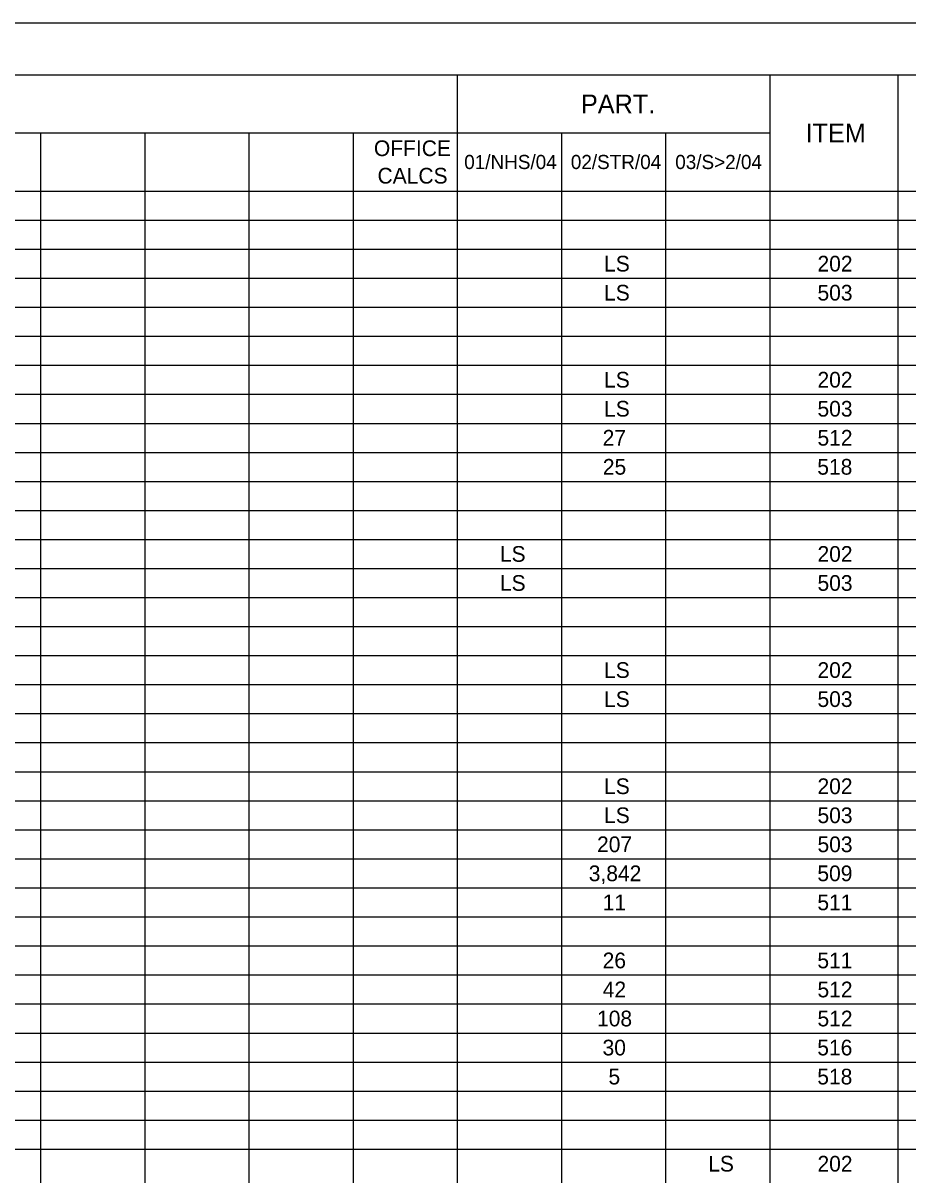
# Model space of a CAD drawing. Extents: x 0 to 34, y 0 to 22.
# Drawn here: x 8.36 to 16.9, y 10.89 to 22 of the extents above; entities that cross this region are included whole.
import ezdxf

# ---------------------------------------------------------------- set-up
doc = ezdxf.new("R2010")
doc.units = 0
for name, color, linetype in [('SH_Border', 7, 'Continuous'), ('SH_Cut_Line', 7, 'Continuous'), ('SH_Text', 7, 'Continuous')]:
    doc.layers.add(name, color=color, linetype=linetype)

msp = doc.modelspace()

# ---------------------------------------------------------------- linework, layer by layer
at = {"layer": 'SH_Border'}
msp.add_lwpolyline([(1.5, 21.5), (33.5, 21.5), (33.5, 0.5), (1.5, 0.5)], close=True, dxfattribs=at)
at = {"layer": 'SH_Cut_Line'}
msp.add_lwpolyline([(0, 0), (34, 0), (34, 22), (0, 22)], close=True, dxfattribs=at)
at = {"layer": 'SH_Text'}
for p, q in [((1.5, 21.5), (32, 21.5)), ((12.55, 21.5), (12.55, 0.502)), ((15.564, 21.5), (15.564, 0.502)), ((16.799, 21.5), (16.799, 0.502)), ((1.5, 20.94), (15.564, 20.94)), ((8.532, 20.94), (8.532, 0.502)), ((9.537, 20.94), (9.537, 0.502)), ((10.541, 20.94), (10.541, 0.502)), ((11.546, 20.94), (11.546, 0.502)), ((13.555, 20.94), (13.555, 0.502)), ((14.56, 20.94), (14.56, 0.502)), ((1.5, 20.38), (32, 20.38)), ((1.5, 20.1), (32, 20.1)), ((1.5, 19.82), (32, 19.82)), ((1.5, 19.54), (32, 19.54)), ((1.5, 19.26), (32, 19.26)), ((1.5, 18.98), (32, 18.98)), ((1.5, 18.7), (32, 18.7)), ((1.5, 18.42), (32, 18.42)), ((1.5, 18.14), (32, 18.14)), ((1.5, 17.86), (32, 17.86)), ((1.5, 17.58), (32, 17.58)), ((1.5, 17.3), (32, 17.3)), ((1.5, 17.021), (32, 17.021)), ((1.5, 16.741), (32, 16.741)), ((1.5, 16.461), (32, 16.461)), ((1.5, 16.181), (32, 16.181)), ((1.5, 15.901), (32, 15.901)), ((1.5, 15.621), (32, 15.621)), ((1.5, 15.341), (32, 15.341)), ((1.5, 15.061), (32, 15.061)), ((1.5, 14.781), (32, 14.781)), ((1.5, 14.501), (32, 14.501)), ((1.5, 14.221), (32, 14.221)), ((1.5, 13.941), (32, 13.941)), ((1.5, 13.661), (32, 13.661)), ((1.5, 13.381), (32, 13.381)), ((1.5, 13.101), (32, 13.101)), ((1.5, 12.821), (32, 12.821)), ((1.5, 12.541), (32, 12.541)), ((1.5, 12.261), (32, 12.261)), ((1.5, 11.981), (32, 11.981)), ((1.5, 11.701), (32, 11.701)), ((1.5, 11.421), (32, 11.421)), ((1.5, 11.141), (32, 11.141))]:
    msp.add_line(p, q, dxfattribs=at)

# ---------------------------------------------------------------- texts
for s, height, p in [('PART.', 0.1818, (13.744, 21.129)), ('ITEM', 0.1818, (15.91, 20.849)), ('OFFICE', 0.1515, (11.747, 20.717)), ('01/NHS/04', 0.1364, (12.618, 20.592)), ('02/STR/04', 0.1364, (13.646, 20.592)), ('03/S>2/04', 0.1364, (14.653, 20.592)), ('CALCS', 0.1515, (11.782, 20.452)), ('LS', 0.1515, (13.967, 19.604)), ('202', 0.1515, (16.025, 19.604)), ('LS', 0.1515, (13.967, 19.324)), ('503', 0.1515, (16.025, 19.324)), ('LS', 0.1515, (13.967, 18.485)), ('202', 0.1515, (16.025, 18.485)), ('LS', 0.1515, (13.967, 18.205)), ('503', 0.1515, (16.025, 18.205)), ('27', 0.1515, (13.953, 17.925)), ('512', 0.1515, (16.025, 17.925)), ('25', 0.1515, (13.955, 17.645)), ('518', 0.1515, (16.023, 17.645)), ('LS', 0.1515, (12.962, 16.805)), ('202', 0.1515, (16.025, 16.805)), ('LS', 0.1515, (12.962, 16.525)), ('503', 0.1515, (16.025, 16.525)), ('LS', 0.1515, (13.967, 15.685)), ('202', 0.1515, (16.025, 15.685)), ('LS', 0.1515, (13.967, 15.405)), ('503', 0.1515, (16.025, 15.405)), ('LS', 0.1515, (13.967, 14.565)), ('202', 0.1515, (16.025, 14.565)), ('LS', 0.1515, (13.967, 14.285)), ('503', 0.1515, (16.025, 14.285)), ('207', 0.1515, (13.899, 14.005)), ('503', 0.1515, (16.025, 14.005)), ('3,842', 0.1515, (13.819, 13.725)), ('509', 0.1515, (16.024, 13.725)), ('11', 0.1515, (13.954, 13.445)), ('511', 0.1515, (16.024, 13.445)), ('26', 0.1515, (13.953, 12.885)), ('511', 0.1515, (16.024, 12.885)), ('42', 0.1515, (13.954, 12.605)), ('512', 0.1515, (16.025, 12.605)), ('108', 0.1515, (13.899, 12.325)), ('512', 0.1515, (16.025, 12.325)), ('30', 0.1515, (13.952, 12.045)), ('516', 0.1515, (16.023, 12.045)), ('5', 0.152, (14.009, 11.765)), ('518', 0.1515, (16.023, 11.765)), ('LS', 0.1515, (14.971, 10.925)), ('202', 0.1515, (16.025, 10.925))]:
    msp.add_text(s, height=height, dxfattribs=at).set_placement(p)

doc.saveas('drawing.dxf')
